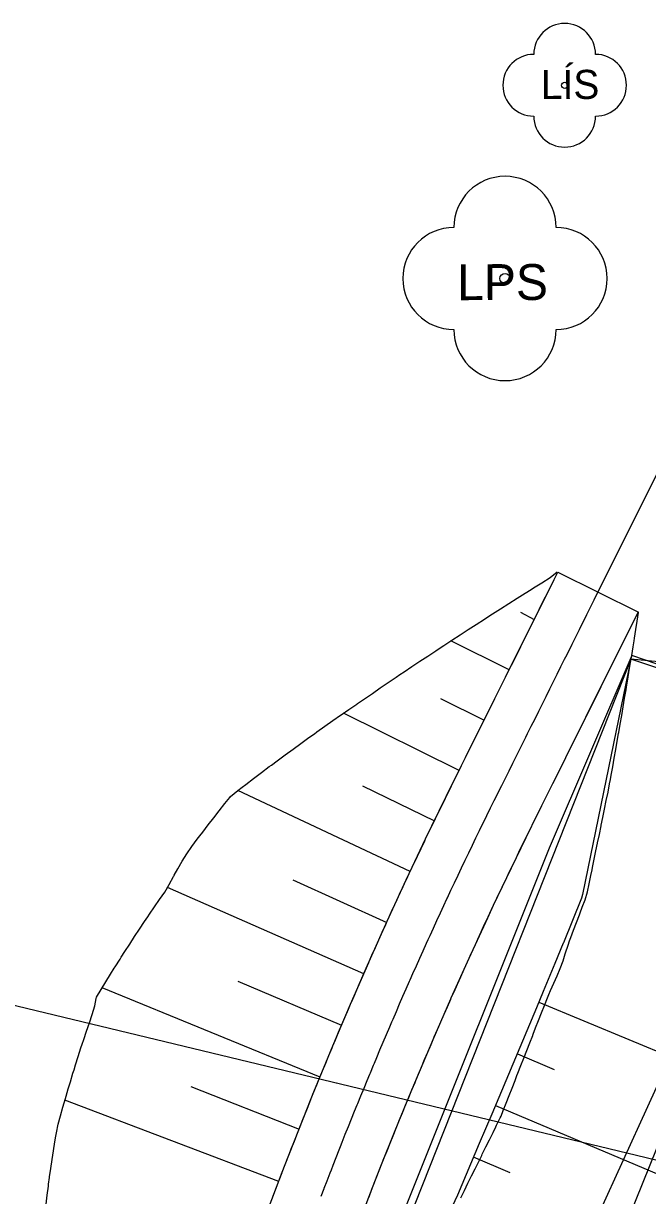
# Model space of a CAD drawing. Extents: x -564037 to -563722, y -1163561 to -1163412.
# Drawn here: x -563903.68 to -563889.78, y -1163493.12 to -1163467.02 of the extents above; entities that cross this region are included whole.
import ezdxf

# ---------------------------------------------------------------- set-up
doc = ezdxf.new("R2010")
doc.units = 0
for name, color, linetype in [('5', 7, 'Continuous'), ('Default', 7, 'Continuous'), ('Line', 7, 'Continuous'), ('Vrstva 1', 7, 'Continuous'), ('Vrstva 2', 7, 'Continuous')]:
    doc.layers.add(name, color=color, linetype=linetype)

msp = doc.modelspace()

# ---------------------------------------------------------------- linework, layer by layer
msp.add_line((-563890.151, -1163481.173), (-563898.85, -1163503.099))
for points in [[(-563897.048, -1163493.132), (-563896.982, -1163492.959), (-563896.979, -1163492.953), (-563896.915, -1163492.786), (-563896.849, -1163492.614), (-563896.82, -1163492.541), (-563896.781, -1163492.441), (-563896.714, -1163492.269), (-563896.646, -1163492.097), (-563896.617, -1163492.021), (-563896.578, -1163491.925), (-563896.51, -1163491.753), (-563896.442, -1163491.581), (-563896.373, -1163491.409), (-563896.303, -1163491.238), (-563896.245, -1163491.093), (-563896.234, -1163491.066), (-563896.164, -1163490.895), (-563896.094, -1163490.724), (-563896.023, -1163490.553), (-563895.967, -1163490.416), (-563895.952, -1163490.382), (-563895.881, -1163490.211), (-563895.863, -1163490.169), (-563895.81, -1163490.04), (-563895.738, -1163489.87), (-563895.666, -1163489.7), (-563895.593, -1163489.529), (-563895.521, -1163489.359), (-563895.473, -1163489.248), (-563895.447, -1163489.189), (-563895.374, -1163489.019), (-563895.3, -1163488.85), (-563895.226, -1163488.68), (-563895.152, -1163488.511), (-563895.078, -1163488.342), (-563895.073, -1163488.331), (-563895.064, -1163488.311), (-563895.003, -1163488.172), (-563894.927, -1163488.003), (-563894.852, -1163487.835), (-563894.776, -1163487.666), (-563894.7, -1163487.497), (-563894.664, -1163487.419), (-563894.623, -1163487.329), (-563894.546, -1163487.16), (-563894.469, -1163486.992), (-563894.392, -1163486.824), (-563894.314, -1163486.656), (-563894.246, -1163486.51), (-563894.236, -1163486.489), (-563894.158, -1163486.321), (-563894.114, -1163486.228), (-563894.079, -1163486.154), (-563894, -1163485.986), (-563893.921, -1163485.819), (-563893.841, -1163485.652), (-563893.819, -1163485.606), (-563893.761, -1163485.485), (-563893.681, -1163485.319), (-563893.601, -1163485.152), (-563893.52, -1163484.986), (-563893.439, -1163484.819), (-563893.383, -1163484.706), (-563893.357, -1163484.653), (-563893.275, -1163484.487), (-563893.193, -1163484.322), (-563893.116, -1163484.167), (-563893.111, -1163484.156), (-563893.028, -1163483.99), (-563892.946, -1163483.825), (-563892.939, -1163483.81), (-563892.863, -1163483.659), (-563892.781, -1163483.494), (-563892.698, -1163483.328), (-563892.616, -1163483.162), (-563892.533, -1163482.997), (-563892.493, -1163482.915), (-563892.451, -1163482.831), (-563892.368, -1163482.666), (-563892.286, -1163482.5), (-563892.203, -1163482.335), (-563892.121, -1163482.169), (-563892.047, -1163482.02), (-563892.038, -1163482.003), (-563891.956, -1163481.838), (-563891.873, -1163481.672), (-563891.791, -1163481.507), (-563891.708, -1163481.341), (-563891.626, -1163481.175), (-563891.601, -1163481.125), (-563891.543, -1163481.01), (-563891.461, -1163480.844), (-563891.378, -1163480.679), (-563891.296, -1163480.513), (-563891.213, -1163480.347), (-563891.155, -1163480.23), (-563891.131, -1163480.182), (-563891.048, -1163480.016), (-563890.966, -1163479.851), (-563889.152, -1163476.21)], [(-563903.174, -1163493.306), (-563903.149, -1163493.108), (-563903.123, -1163492.909), (-563903.117, -1163492.865), (-563903.096, -1163492.711), (-563903.095, -1163492.703), (-563903.068, -1163492.513), (-563903.039, -1163492.315), (-563903.009, -1163492.117), (-563902.977, -1163491.919), (-563902.957, -1163491.796), (-563902.945, -1163491.722), (-563902.905, -1163491.528), (-563902.853, -1163491.338), (-563902.799, -1163491.148), (-563902.745, -1163490.959), (-563902.69, -1163490.77), (-563902.688, -1163490.764), (-563902.633, -1163490.581), (-563902.576, -1163490.393), (-563902.552, -1163490.314), (-563902.517, -1163490.205), (-563902.458, -1163490.017), (-563902.398, -1163489.83), (-563902.371, -1163489.748), (-563902.336, -1163489.643), (-563902.274, -1163489.457), (-563902.21, -1163489.27), (-563902.146, -1163489.084), (-563902.089, -1163488.895), (-563902.058, -1163488.729), (-563902.049, -1163488.699), (-563901.946, -1163488.529), (-563901.843, -1163488.359), (-563901.738, -1163488.19), (-563901.654, -1163488.055), (-563901.633, -1163488.021), (-563901.527, -1163487.852), (-563901.5, -1163487.811), (-563901.42, -1163487.684), (-563901.312, -1163487.517), (-563901.203, -1163487.35), (-563901.093, -1163487.184), (-563900.983, -1163487.018), (-563900.91, -1163486.909), (-563900.871, -1163486.852), (-563900.759, -1163486.687), (-563900.646, -1163486.523), (-563900.532, -1163486.359), (-563900.431, -1163486.189), (-563900.337, -1163486.017), (-563900.331, -1163486.007), (-563900.32, -1163485.987), (-563900.241, -1163485.846), (-563900.144, -1163485.675), (-563900.042, -1163485.506), (-563899.926, -1163485.344), (-563899.806, -1163485.184), (-563899.75, -1163485.11), (-563899.685, -1163485.024), (-563899.563, -1163484.865), (-563899.44, -1163484.707), (-563899.317, -1163484.549), (-563899.193, -1163484.392), (-563899.084, -1163484.255), (-563899.068, -1163484.235), (-563898.901, -1163484.098), (-563898.805, -1163484.023), (-563898.727, -1163483.964), (-563898.553, -1163483.832), (-563898.379, -1163483.7), (-563898.203, -1163483.568), (-563898.155, -1163483.532), (-563898.028, -1163483.437), (-563897.851, -1163483.307), (-563897.675, -1163483.178), (-563897.498, -1163483.049), (-563897.32, -1163482.921), (-563897.199, -1163482.834), (-563897.142, -1163482.793), (-563896.963, -1163482.666), (-563896.785, -1163482.54), (-563896.617, -1163482.422), (-563896.606, -1163482.415), (-563896.432, -1163482.295), (-563896.257, -1163482.175), (-563896.242, -1163482.164), (-563896.083, -1163482.055), (-563895.908, -1163481.936), (-563895.732, -1163481.816), (-563895.556, -1163481.697), (-563895.38, -1163481.578), (-563895.293, -1163481.52), (-563895.203, -1163481.46), (-563895.026, -1163481.341), (-563894.849, -1163481.223), (-563894.671, -1163481.105), (-563894.493, -1163480.987), (-563894.332, -1163480.882), (-563894.314, -1163480.87), (-563894.135, -1163480.752), (-563893.955, -1163480.635), (-563893.775, -1163480.518), (-563893.595, -1163480.401), (-563893.414, -1163480.285), (-563893.359, -1163480.249), (-563893.232, -1163480.168), (-563893.051, -1163480.052), (-563892.869, -1163479.936), (-563892.686, -1163479.82), (-563892.503, -1163479.705), (-563892.374, -1163479.623), (-563892.32, -1163479.589), (-563892.136, -1163479.474), (-563891.952, -1163479.359), (-563891.79, -1163479.234)], [(-563898.27, -1163493.54), (-563897.913, -1163492.595), (-563897.753, -1163492.179), (-563897.547, -1163491.654), (-563897.269, -1163490.958), (-563897.171, -1163490.716), (-563896.89, -1163490.033), (-563896.786, -1163489.783), (-563896.391, -1163488.853), (-563895.988, -1163487.927), (-563895.979, -1163487.907), (-563895.575, -1163487.005), (-563895.153, -1163486.088), (-563895.019, -1163485.803), (-563894.721, -1163485.175), (-563894.281, -1163484.266), (-563894.011, -1163483.721), (-563893.834, -1163483.364), (-563893.388, -1163482.469), (-563892.942, -1163481.574), (-563892.496, -1163480.679), (-563892.461, -1163480.609), (-563892.05, -1163479.784), (-563891.777, -1163479.236)], [(-563898.115, -1163493.125), (-563898.048, -1163492.95), (-563897.982, -1163492.775), (-563897.915, -1163492.601), (-563897.913, -1163492.595), (-563897.848, -1163492.426), (-563897.781, -1163492.252), (-563897.753, -1163492.179), (-563897.713, -1163492.078), (-563897.645, -1163491.904), (-563897.577, -1163491.73), (-563897.547, -1163491.654), (-563897.508, -1163491.556), (-563897.439, -1163491.383), (-563897.37, -1163491.209), (-563897.3, -1163491.036), (-563897.23, -1163490.862), (-563897.171, -1163490.716), (-563897.16, -1163490.689), (-563897.089, -1163490.516), (-563897.018, -1163490.343), (-563896.947, -1163490.171), (-563896.89, -1163490.033), (-563896.876, -1163489.998), (-563896.804, -1163489.826), (-563896.786, -1163489.783), (-563896.732, -1163489.653), (-563896.659, -1163489.481), (-563896.586, -1163489.309), (-563896.513, -1163489.137), (-563896.44, -1163488.965), (-563896.391, -1163488.853), (-563896.366, -1163488.794), (-563896.292, -1163488.622), (-563896.217, -1163488.451), (-563896.143, -1163488.279), (-563896.068, -1163488.108), (-563895.992, -1163487.937), (-563895.988, -1163487.927), (-563895.979, -1163487.907), (-563895.917, -1163487.766), (-563895.841, -1163487.596), (-563895.764, -1163487.425), (-563895.688, -1163487.255), (-563895.611, -1163487.085), (-563895.575, -1163487.005), (-563895.533, -1163486.914), (-563895.456, -1163486.744), (-563895.378, -1163486.575), (-563895.3, -1163486.405), (-563895.221, -1163486.235), (-563895.153, -1163486.088), (-563895.142, -1163486.066), (-563895.063, -1163485.897), (-563895.019, -1163485.803), (-563894.984, -1163485.728), (-563894.904, -1163485.559), (-563894.824, -1163485.39), (-563894.743, -1163485.221), (-563894.721, -1163485.175), (-563894.663, -1163485.053), (-563894.582, -1163484.884), (-563894.5, -1163484.716), (-563894.419, -1163484.548), (-563894.337, -1163484.38), (-563894.281, -1163484.266), (-563894.255, -1163484.212), (-563894.172, -1163484.045), (-563894.089, -1163483.877), (-563894.011, -1163483.721), (-563894.006, -1163483.71), (-563893.923, -1163483.544), (-563893.841, -1163483.379), (-563893.834, -1163483.364), (-563893.758, -1163483.213), (-563893.676, -1163483.048), (-563893.593, -1163482.882), (-563893.511, -1163482.716), (-563893.428, -1163482.551), (-563893.388, -1163482.469), (-563893.346, -1163482.385), (-563893.263, -1163482.22), (-563893.181, -1163482.054), (-563893.098, -1163481.889), (-563893.016, -1163481.723), (-563892.942, -1163481.574), (-563892.933, -1163481.557), (-563892.851, -1163481.392), (-563892.768, -1163481.226), (-563892.686, -1163481.061), (-563892.603, -1163480.895), (-563892.521, -1163480.729), (-563892.496, -1163480.679), (-563892.438, -1163480.564), (-563892.356, -1163480.398), (-563892.273, -1163480.233), (-563892.191, -1163480.067), (-563892.108, -1163479.902), (-563892.05, -1163479.784), (-563892.026, -1163479.736), (-563891.943, -1163479.57), (-563891.861, -1163479.405), (-563891.778, -1163479.239), (-563891.777, -1163479.236), (-563889.979, -1163480.131)], [(-563896.046, -1163493.311), (-563895.888, -1163492.903), (-563895.687, -1163492.389), (-563895.414, -1163491.706), (-563895.318, -1163491.47), (-563895.043, -1163490.8), (-563894.941, -1163490.555), (-563894.554, -1163489.643), (-563894.158, -1163488.736), (-563894.15, -1163488.716), (-563893.754, -1163487.832), (-563893.34, -1163486.933), (-563893.209, -1163486.653), (-563892.917, -1163486.038), (-563892.485, -1163485.147), (-563892.221, -1163484.613), (-563892.044, -1163484.256), (-563891.598, -1163483.361), (-563891.152, -1163482.466), (-563890.706, -1163481.571), (-563890.671, -1163481.5), (-563890.26, -1163480.676), (-563889.986, -1163480.127)], [(-563895.982, -1163493.146), (-563895.916, -1163492.975), (-563895.888, -1163492.903), (-563895.85, -1163492.804), (-563895.783, -1163492.634), (-563895.716, -1163492.463), (-563895.687, -1163492.389), (-563895.649, -1163492.293), (-563895.581, -1163492.123), (-563895.513, -1163491.953), (-563895.445, -1163491.783), (-563895.376, -1163491.613), (-563895.318, -1163491.47), (-563895.308, -1163491.443), (-563895.238, -1163491.274), (-563895.169, -1163491.104), (-563895.099, -1163490.935), (-563895.043, -1163490.8), (-563895.029, -1163490.766), (-563894.958, -1163490.597), (-563894.941, -1163490.555), (-563894.888, -1163490.428), (-563894.817, -1163490.259), (-563894.745, -1163490.09), (-563894.673, -1163489.922), (-563894.601, -1163489.753), (-563894.554, -1163489.643), (-563894.529, -1163489.585), (-563894.456, -1163489.417), (-563894.384, -1163489.249), (-563894.31, -1163489.081), (-563894.237, -1163488.913), (-563894.163, -1163488.746), (-563894.158, -1163488.736), (-563894.15, -1163488.716), (-563894.089, -1163488.578), (-563894.014, -1163488.411), (-563893.939, -1163488.244), (-563893.864, -1163488.077), (-563893.789, -1163487.91), (-563893.754, -1163487.832), (-563893.713, -1163487.743), (-563893.637, -1163487.576), (-563893.561, -1163487.41), (-563893.484, -1163487.244), (-563893.407, -1163487.077), (-563893.34, -1163486.933), (-563893.33, -1163486.911), (-563893.252, -1163486.746), (-563893.209, -1163486.653), (-563893.174, -1163486.58), (-563893.096, -1163486.414), (-563893.018, -1163486.249), (-563892.939, -1163486.083), (-563892.917, -1163486.038), (-563892.86, -1163485.918), (-563892.78, -1163485.753), (-563892.701, -1163485.588), (-563892.621, -1163485.423), (-563892.54, -1163485.259), (-563892.485, -1163485.147), (-563892.46, -1163485.094), (-563892.379, -1163484.93), (-563892.297, -1163484.766), (-563892.221, -1163484.613), (-563892.216, -1163484.602), (-563892.133, -1163484.436), (-563892.051, -1163484.271), (-563892.044, -1163484.256), (-563891.968, -1163484.105), (-563891.886, -1163483.94), (-563891.803, -1163483.774), (-563891.721, -1163483.608), (-563891.638, -1163483.443), (-563891.598, -1163483.361), (-563891.556, -1163483.277), (-563891.473, -1163483.112), (-563891.391, -1163482.946), (-563891.308, -1163482.78), (-563891.226, -1163482.615), (-563891.152, -1163482.466), (-563891.143, -1163482.449), (-563891.061, -1163482.284), (-563890.978, -1163482.118), (-563890.896, -1163481.953), (-563890.813, -1163481.787), (-563890.731, -1163481.621), (-563890.706, -1163481.571), (-563890.648, -1163481.456), (-563890.566, -1163481.29), (-563890.483, -1163481.125), (-563890.401, -1163480.959), (-563890.318, -1163480.793), (-563890.26, -1163480.676), (-563890.236, -1163480.628), (-563890.153, -1163480.462), (-563890.071, -1163480.297), (-563889.988, -1163480.131), (-563889.986, -1163480.127)], [(-563893.939, -1163493.164), (-563893.904, -1163493.093), (-563893.859, -1163493.002), (-563893.779, -1163492.841), (-563893.699, -1163492.679), (-563893.619, -1163492.518), (-563893.539, -1163492.357), (-563893.471, -1163492.221), (-563893.459, -1163492.196), (-563893.379, -1163492.035), (-563893.299, -1163491.873), (-563893.22, -1163491.712), (-563893.157, -1163491.583), (-563893.141, -1163491.55), (-563893.062, -1163491.389), (-563893.042, -1163491.349), (-563892.992, -1163491.224), (-563892.927, -1163491.057), (-563892.862, -1163490.889), (-563892.797, -1163490.722), (-563892.731, -1163490.555), (-563892.689, -1163490.446), (-563892.666, -1163490.388), (-563892.6, -1163490.221), (-563892.535, -1163490.054), (-563892.469, -1163489.886), (-563892.404, -1163489.719), (-563892.338, -1163489.552), (-563892.334, -1163489.542), (-563892.326, -1163489.522), (-563892.272, -1163489.385), (-563892.207, -1163489.218), (-563892.141, -1163489.051), (-563892.075, -1163488.883), (-563892.009, -1163488.716), (-563891.977, -1163488.639), (-563891.939, -1163488.551), (-563891.867, -1163488.386), (-563891.794, -1163488.222), (-563891.722, -1163488.058), (-563891.66, -1163487.888), (-563891.613, -1163487.738), (-563891.606, -1163487.716), (-563891.55, -1163487.543), (-563891.517, -1163487.448), (-563891.489, -1163487.373), (-563891.425, -1163487.205), (-563891.361, -1163487.036), (-563891.297, -1163486.868), (-563891.28, -1163486.821), (-563891.233, -1163486.699), (-563891.169, -1163486.53), (-563891.117, -1163486.356), (-563891.079, -1163486.174), (-563891.042, -1163485.992), (-563891.016, -1163485.868), (-563891.004, -1163485.81), (-563890.967, -1163485.627), (-563890.929, -1163485.445), (-563890.893, -1163485.274), (-563890.891, -1163485.262), (-563890.852, -1163485.075), (-563890.813, -1163484.888), (-563890.81, -1163484.871), (-563890.774, -1163484.7), (-563890.736, -1163484.513), (-563890.698, -1163484.325), (-563890.66, -1163484.137), (-563890.624, -1163483.948), (-563890.607, -1163483.855), (-563890.59, -1163483.759), (-563890.556, -1163483.569), (-563890.522, -1163483.379), (-563890.488, -1163483.189), (-563890.455, -1163482.999), (-563890.425, -1163482.828), (-563890.422, -1163482.809), (-563890.389, -1163482.619), (-563890.356, -1163482.428), (-563890.324, -1163482.238), (-563890.291, -1163482.047), (-563890.259, -1163481.856), (-563890.25, -1163481.799), (-563890.227, -1163481.666), (-563890.196, -1163481.475), (-563890.164, -1163481.284), (-563890.133, -1163481.092), (-563890.102, -1163480.901), (-563890.08, -1163480.766), (-563890.071, -1163480.71), (-563890.041, -1163480.518), (-563890.01, -1163480.327), (-563889.98, -1163480.135), (-563889.979, -1163480.131)], [(-563878.137, -1163496.97), (-563876.837, -1163490), (-563879.296, -1163487.066), (-563881.987, -1163484.651), (-563882.119, -1163484.582), (-563882.455, -1163484.408), (-563883.788, -1163483.304), (-563883.864, -1163483.279), (-563884.159, -1163483.181), (-563884.226, -1163483.159), (-563884.302, -1163483.134), (-563884.34, -1163483.121), (-563884.386, -1163483.106), (-563884.482, -1163483.074), (-563884.592, -1163483.038), (-563884.718, -1163482.996), (-563884.865, -1163482.947), (-563884.978, -1163482.91), (-563885.376, -1163482.786), (-563885.4, -1163482.777), (-563885.486, -1163482.747), (-563885.596, -1163482.707), (-563890.151, -1163481.173)], [(-563882.19, -1163496.364), (-563880.778, -1163492.835), (-563880.808, -1163489.502), (-563880.527, -1163488.546), (-563880.34, -1163487.91), (-563881.995, -1163486.424), (-563882.215, -1163486.31), (-563882.772, -1163486.021), (-563884.984, -1163484.19), (-563885.111, -1163484.148), (-563885.233, -1163484.108), (-563885.348, -1163484.069), (-563885.478, -1163484.026), (-563885.544, -1163484.004), (-563885.623, -1163483.978), (-563885.788, -1163483.923), (-563887.164, -1163483.863), (-563888.153, -1163487.579), (-563890.867, -1163493.518)]]:
    msp.add_lwpolyline(points)
for points in [[(-563900.324, -1163505.882), (-563892.678, -1163503.006), (-563888.735, -1163501.906), (-563886.271, -1163502.018), (-563883.536, -1163500.684), (-563878.095, -1163497.234), (-563876.621, -1163489.849), (-563880.163, -1163485.998), (-563881.977, -1163484.515), (-563883.765, -1163483.269), (-563890.133, -1163481.092), (-563891.974, -1163485.382), (-563895.143, -1163493.304), (-563898.704, -1163502.458), (-563900.439, -1163505.855)], [(-563887.058, -1163484.593), (-563887.855, -1163487.81), (-563890.21, -1163493.633), (-563891.581, -1163498.253), (-563891.461, -1163499.576), (-563890.275, -1163499.82), (-563886.599, -1163499.649), (-563882.84, -1163497.558), (-563881.049, -1163492.941), (-563880.784, -1163487.979), (-563884.81, -1163484.679), (-563886.418, -1163484.198)]]:
    msp.add_lwpolyline(points, close=True)
at = {"layer": '5'}
msp.add_line((-563904.23, -1163488.796), (-563873.359, -1163496.24), dxfattribs=at)
at = {"layer": 'Default'}
msp.add_lwpolyline([(-563886.832, -1163481.493), (-563890.151, -1163481.173), (-563890.761, -1163484.133), (-563891.23, -1163486.411), (-563891.248, -1163486.496), (-563891.655, -1163487.489), (-563891.658, -1163487.497), (-563891.845, -1163487.951), (-563892.101, -1163488.575), (-563892.249, -1163488.936), (-563893.249, -1163491.302), (-563893.527, -1163491.96), (-563894.011, -1163493.107), (-563894.298, -1163493.726)], dxfattribs=at)
at = {"layer": 'Line'}
for p, q in [((-563892.611, -1163480.131), (-563892.304, -1163480.294)), ((-563892.862, -1163481.413), (-563894.158, -1163480.767)), ((-563894.39, -1163482.049), (-563893.419, -1163482.532)), ((-563893.976, -1163483.651), (-563896.552, -1163482.378)), ((-563895.065, -1163485.902), (-563898.905, -1163484.101)), ((-563896.131, -1163483.997), (-563894.527, -1163484.773)), ((-563896.097, -1163488.179), (-563900.473, -1163486.259)), ((-563897.68, -1163486.088), (-563895.588, -1163487.037)), ((-563898.903, -1163488.346), (-563896.592, -1163489.326)), ((-563897.073, -1163490.48), (-563901.924, -1163488.492)), ((-563892.197, -1163488.809), (-563887.537, -1163490.746)), ((-563891.855, -1163490.315), (-563892.672, -1163489.966)), ((-563899.953, -1163490.686), (-563897.541, -1163491.639)), ((-563897.992, -1163492.805), (-563902.755, -1163490.993)), ((-563893.169, -1163491.112), (-563888.462, -1163493.101)), ((-563892.838, -1163492.613), (-563893.655, -1163492.264))]:
    msp.add_line(p, q, dxfattribs=at)
at = {"layer": 'Vrstva 2'}
for centre, radius in [((-563891.625, -1163468.399), 0.0688), ((-563892.954, -1163472.701), 0.114)]:
    msp.add_circle(centre, radius, dxfattribs=at)
for centre, radius, start, end in [((-563891.625, -1163467.711), 0.688, 0, 180), ((-563892.313, -1163468.399), 0.688, 90, 270), ((-563890.937, -1163468.399), 0.688, 270, 90), ((-563891.625, -1163469.087), 0.688, 180, 0), ((-563892.954, -1163471.563), 1.137, 0, 180), ((-563894.092, -1163472.701), 1.137, 90, 270), ((-563891.817, -1163472.701), 1.137, 270, 90), ((-563892.954, -1163473.838), 1.137, 180, 0)]:
    msp.add_arc(centre, radius, start, end, dxfattribs=at)

# ---------------------------------------------------------------- texts
at = {"layer": 'Vrstva 1'}
for s, height, p in [('LÍS', 0.648, (-563892.153, -1163468.707)), ('LPS', 0.8, (-563894.019, -1163473.184))]:
    msp.add_text(s, height=height, rotation=0.1546, dxfattribs=at).set_placement(p)

doc.saveas('drawing.dxf')
